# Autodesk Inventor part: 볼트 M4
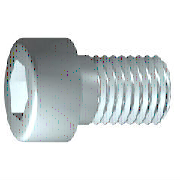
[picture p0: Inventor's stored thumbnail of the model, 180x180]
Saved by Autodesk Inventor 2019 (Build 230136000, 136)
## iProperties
IsCustomPart: 0
Created: 2014-10
Part Number: 볼트 M4
Material: 강철, 연강
Description: 6각머리 태핑 나사
Document SubType Name: Modeling
Standard: KS B 1003
Designer: KYOUNG IL JANG
Standards Organization: KS
Language: ko-KR
Size Designation: M 4 x 10
Categories: <MemberInstance><Categories><Category DisplayName="조임쇠" InternalName="e4da775c-781d-43d5-af7c-5136215cf5a6" Mnemonic="FSTN"><Category DisplayName="볼트" InternalN
Density: 7.86 g/cm^3
Mass: 2.0371 g
Surface Area: 3.0572 cm^2
Volume: 0.259174 cm^3
Appearance: 강철 - 광택
Author: SeoGD™ [www.esajin.kr]
Revision Number: 1
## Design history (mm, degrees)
sketch "스케치1"
  geometry: L1 (-1, 0)-(10, 0); L2 (10, 0)-(10, 2); L3 (10, 2)-(1.75, 2); L4 (1.75, 2)-(1.32, 2); L5 (1.32, 2)-(0, 2); L6 (0, 2)-(0, 3.5); L7 (0, 3.5)-(-4, 3.5); L8 (-4, 3.5)-(-4, 1.732); L9 (-4, 1.732)-(-2, 1.732); L10 (-2, 1.732)-(-1, 0); L11 (-6.8, 0)-(12.8, 0) reference; L12 (0, -0.7)-(0, 4.2) reference; L13 (1.75, 2)-(0, 2)
  constraints: 22 end point, 6 parallel, 2 collinear, 2 perpendicular, 1 horizontal, 1 point on line
  dimensions: "d1" = 8.25 distance from line of L3.end L2 (= GEL); "d2" = 0.42952 distance of L4.end L3.end (computed from GAL); "d3" = 4 distance between parallel lines of L8 L6 (= KOH); "d4" = 2 distance of L8.end L9.end (= INTI); "d5" = 60 deg angle of L10 L1; "d6" = 4 diameter of L3 L1 (= GD); "d7" = 4 diameter of L5 L1 (= BDM); "d8" = 3.4641 diameter of L9 L1 (= 1.1547 x SW); "d9" = 7 diameter of L7 L1 (= KOD); "d26" = 10 distance between parallel lines of L12 L2 (= NLG)
revolve "본체" sketch "스케치1" stored, may be unused: angle "d10" = 90 deg
sketch "스케치2"
  geometry: L1 (0, -4.9)-(0, 4.9) reference; L2 (-4.9, 0)-(4.9, 0) reference; L3 (1.732, 0)-(0.866, -1.5); L4 (0.866, -1.5)-(-0.866, -1.5); L5 (-0.866, -1.5)-(-1.732, 0); L6 (-1.732, 0)-(-0.866, 1.5); L7 (-0.866, 1.5)-(0.866, 1.5); L8 (0.866, 1.5)-(1.732, 0); 2 further points
  constraints: 12 end point, 1 coincident, 1 horizontal alignment, 1 point on line, 12 other
extrude "슬롯" join sketch "스케치2" stored distance "d11" = 10; taper "d12" = 0 deg
workplane "Work Plane1"
fillet "Fillet2" dims "d30" = 0.1 (= R)
body "Solid1"
fillet "모깎기1" dims "d17" = 0.4 (= RR)
feature "스레드" dims "d13" = 8.25 (= GEL), "d14" = 0
chamfer "모따기1" distance "d15" = 0.42941 (= -0.5 x SPD + 0.5 x GD); stored, may be unused: second distance "d16" = 0.42941 (= GUL), angle "d27" = 45 deg
other parameters: "GD" = 4 (= NND) [user parameter; used in 2 equation terms], "NLG" = 10 [user parameter; used in 1 equation term], "GEL" = 8.25 [user parameter; used in 2 equation terms], "KOD" = 7 [user parameter; used in 1 equation term], "KOH" = 4 [user parameter; used in 1 equation term], "INTI" = 2 [user parameter; used in 1 equation term], "GAL" = 0.42941 (= 0.61345 x PTC) [user parameter; used in 1 equation term], "GUL" = 0.42941 (= 0.61345 x PTC) [user parameter; used in 1 equation term], "BDM" = 4 (= NND) [user parameter; used in 1 equation term], "SW" = 3 [user parameter; used in 2 equation terms], "RR" = 0.4 [user parameter; used in 1 equation term], "SPD" = 3.14117 (= NND - 1.2269 x PTC) [user parameter; used in 1 equation term], "d19" = 0, "d28" = 0, "d29" = 0, "R" = 0.1 [user parameter; used in 1 equation term], "PHH" = 0.2 [user parameter], "GD1" = 3.14117 (= THREADDIA - 1.2269 x PTC) [user parameter], "THREADDIA" = 4 [user parameter; used in 1 equation term], "FAWI" = 45 deg [user parameter], "TPU" = 14.28571 (computed from PTC) [user parameter], "PTC" = 0.7 [user parameter; used in 5 equation terms], "NND" = 4 [user parameter; used in 3 equation terms], "TOA" = 30 deg [user parameter], "E0" = 3.465 (= 1.155 x SW) [user parameter]
